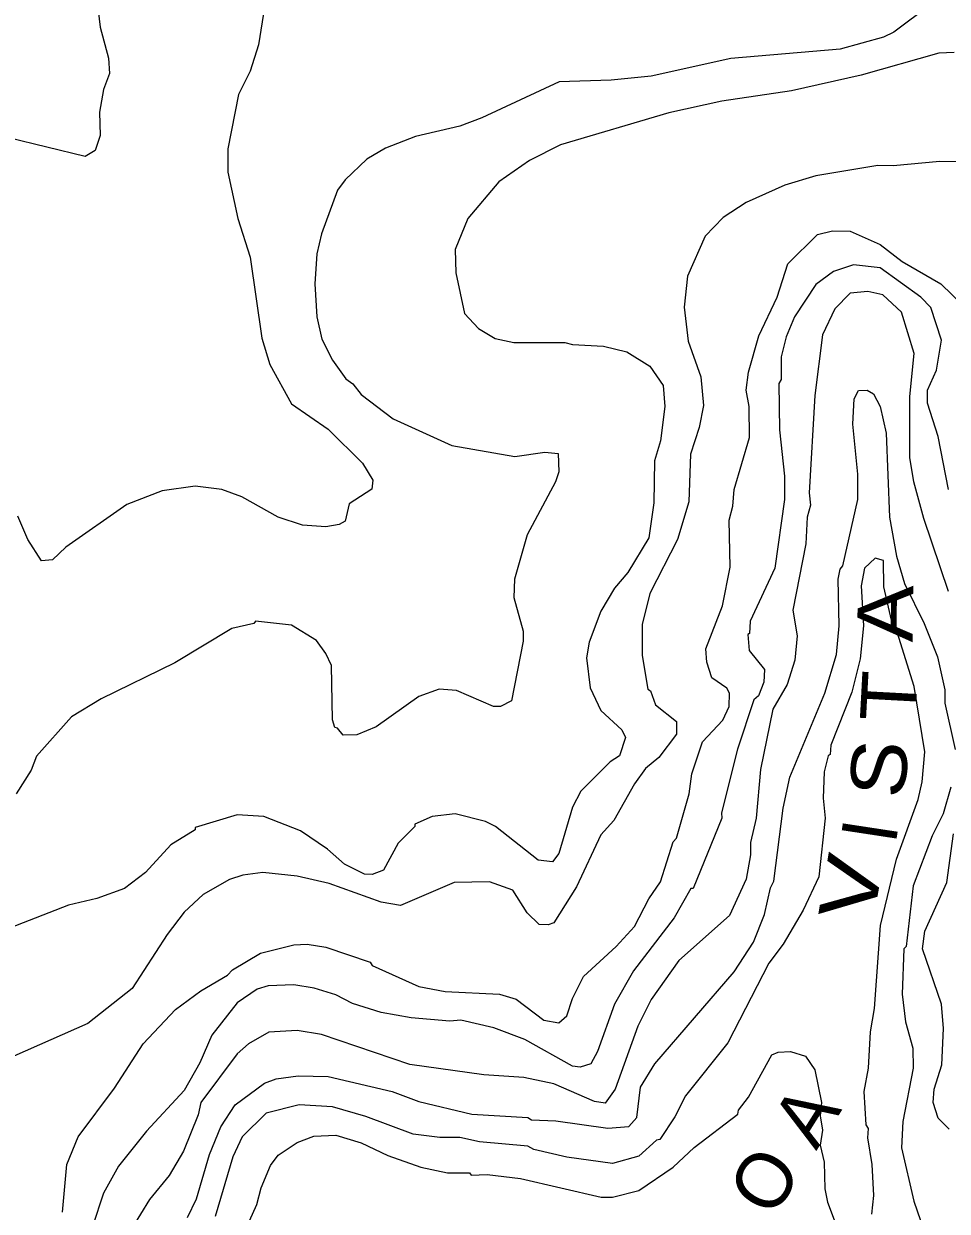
# Model space of a CAD drawing. Extents: x 265.7 to 292.1, y 7676.2 to 7704.2.
# Drawn here: x 274.191 to 275.523, y 7682.175 to 7683.888 of the extents above; entities that cross this region are included whole.
import ezdxf
from ezdxf.enums import TextEntityAlignment as Align

# ---------------------------------------------------------------- set-up
doc = ezdxf.new("R2010")
doc.units = 0
doc.header["$LTSCALE"] = 0.032
doc.layers.add('1', color=7, linetype='Continuous', lineweight=25)
doc.layers.add('2', color=7, linetype='Continuous', lineweight=13)
doc.layers.add('61', color=7, linetype='Continuous')

msp = doc.modelspace()

# ---------------------------------------------------------------- linework, layer by layer
at = {"layer": '1'}
for points in [[(275.4995, 7683.9157), (275.446, 7683.8758), (275.4309, 7683.8686), (275.3686, 7683.8511), (275.2106, 7683.8375), (275.0957, 7683.812), (275.0383, 7683.8064), (274.9633, 7683.804), (274.8515, 7683.7521), (274.8196, 7683.7402), (274.7558, 7683.725), (274.7127, 7683.7082), (274.6856, 7683.6923), (274.6544, 7683.6628), (274.6433, 7683.6476), (274.6201, 7683.5846), (274.6137, 7683.5558), (274.6105, 7683.5127), (274.6137, 7683.4649), (274.6209, 7683.433), (274.6361, 7683.4026), (274.6552, 7683.3755), (274.6656, 7683.3683), (274.6776, 7683.3531), (274.7239, 7683.318), (274.8085, 7683.2797), (274.8994, 7683.2638)], [(275.525, 7683.0691), (275.4891, 7683.1744), (275.4747, 7683.2271), (275.4692, 7683.2622), (275.4692, 7683.35), (275.4755, 7683.4122), (275.4572, 7683.472), (275.4301, 7683.4968), (275.4085, 7683.5016), (275.383, 7683.4992), (275.3606, 7683.4768), (275.3431, 7683.4393), (275.3319, 7683.3516), (275.3239, 7683.2111), (275.3255, 7683.1936), (275.3207, 7683.176), (275.3191, 7683.1377), (275.3, 7683.0419), (275.3064, 7683.0052), (275.3032, 7682.9701), (275.292, 7682.935), (275.2713, 7682.8991), (275.2537, 7682.8121), (275.2473, 7682.7419), (275.2393, 7682.7068), (275.2393, 7682.6893), (275.233, 7682.6541), (275.209, 7682.6015), (275.1356, 7682.5368), (275.0957, 7682.4802), (275.0766, 7682.4419), (275.0438, 7682.3509), (275.0295, 7682.331), (275.0143, 7682.3333), (274.9553, 7682.3589), (274.9122, 7682.3677), (274.8547, 7682.3716), (274.7478, 7682.3868), (274.6201, 7682.4299), (274.585, 7682.4355), (274.5443, 7682.4331), (274.5148, 7682.4163), (274.4988, 7682.402), (274.4462, 7682.3318), (274.4422, 7682.3142), (274.4214, 7682.2615), (274.4007, 7682.2264), (274.372, 7682.1921), (274.3464, 7682.1498)], [(274.8994, 7683.2638), (274.9425, 7683.2701), (274.9617, 7683.2678), (274.9625, 7683.2414), (274.9577, 7683.2271), (274.917, 7683.1505), (274.8986, 7683.0866)], [(274.8986, 7683.0866), (274.8978, 7683.0603), (274.9114, 7683.0116), (274.9114, 7682.9973), (274.8946, 7682.9111), (274.8787, 7682.9031), (274.8683, 7682.9031), (274.8148, 7682.9262), (274.7901, 7682.9278), (274.7606, 7682.9175), (274.6991, 7682.8736), (274.6712, 7682.8624), (274.6513, 7682.8616), (274.6433, 7682.872), (274.6393, 7682.8728), (274.6361, 7682.884), (274.6345, 7682.9621), (274.6265, 7682.9797), (274.613, 7682.9981), (274.577, 7683.0204), (274.5252, 7683.026), (274.5228, 7683.0228), (274.4909, 7683.0156), (274.4087, 7682.9661), (274.3025, 7682.9143), (274.2595, 7682.8879), (274.2092, 7682.8313), (274.2012, 7682.8113), (274.1796, 7682.777)], [(275.5258, 7682.2935), (275.5099, 7682.3094), (275.5027, 7682.3318), (275.5043, 7682.3509), (275.5154, 7682.386), (275.5178, 7682.4387), (275.5146, 7682.4738), (275.4875, 7682.5536), (275.4907, 7682.5791), (275.5226, 7682.6494), (275.5322, 7682.7196)]]:
    msp.add_lwpolyline(points, dxfattribs=at)
at = {"layer": '2'}
for points in [[(274.297, 7683.9149), (274.3009, 7683.883), (274.3129, 7683.8383), (274.3145, 7683.816), (274.3057, 7683.7928), (274.3001, 7683.7601), (274.3009, 7683.7266), (274.2938, 7683.7051), (274.2794, 7683.6963), (274.1685, 7683.7234), (274.1334, 7683.7402), (274.0807, 7683.7729), (274.0057, 7683.8375), (273.9259, 7683.8886)], [(274.5379, 7683.9117), (274.5292, 7683.8575), (274.5172, 7683.8192), (274.5004, 7683.7856), (274.4853, 7683.7074), (274.4853, 7683.6739), (274.4996, 7683.6069), (274.5172, 7683.551), (274.534, 7683.4345), (274.5459, 7683.3962), (274.577, 7683.3396), (274.6297, 7683.3029), (274.6792, 7683.2542), (274.6943, 7683.2295), (274.6927, 7683.2167), (274.66, 7683.1952), (274.6544, 7683.1704), (274.6457, 7683.1656), (274.6265, 7683.1624), (274.593, 7683.1648), (274.5579, 7683.176), (274.5052, 7683.2055), (274.4765, 7683.2159), (274.4382, 7683.2207), (274.3903, 7683.2143), (274.3393, 7683.1944), (274.2515, 7683.1329), (274.2323, 7683.1146), (274.2164, 7683.113), (274.1964, 7683.1441), (274.182, 7683.1776)], [(275.533, 7683.8463), (275.5107, 7683.8455), (275.3989, 7683.8136), (275.2984, 7683.7912), (275.1979, 7683.7761), (275.1213, 7683.7593), (274.9649, 7683.713), (274.9202, 7683.6907), (274.8763, 7683.6596), (274.8316, 7683.6069), (274.8132, 7683.5622), (274.814, 7683.5287), (274.8268, 7683.4697), (274.8468, 7683.4481), (274.8707, 7683.4337), (274.8978, 7683.4282), (274.9712, 7683.4282), (274.9824, 7683.425), (275.0271, 7683.4226), (275.0606, 7683.4146), (275.0941, 7683.3938), (275.1133, 7683.3659), (275.1157, 7683.3356), (275.1093, 7683.2861), (275.1005, 7683.2574), (275.0997, 7683.1968), (275.0925, 7683.1465), (275.0622, 7683.0962), (275.043, 7683.0739), (275.0231, 7683.0404), (275.0063, 7682.9957), (275.0024, 7682.9733), (275.0079, 7682.9302), (275.0231, 7682.8975), (275.0534, 7682.8696), (275.059, 7682.8584), (275.0502, 7682.8321), (275.0367, 7682.8233), (274.9944, 7682.781), (274.9824, 7682.7579), (274.9625, 7682.6908), (274.9537, 7682.6789), (274.9329, 7682.6813), (274.8715, 7682.7299), (274.8571, 7682.7371), (274.8132, 7682.7483), (274.7797, 7682.7443), (274.755, 7682.7331), (274.755, 7682.7299), (274.731, 7682.706), (274.7095, 7682.6669), (274.6935, 7682.6605), (274.6824, 7682.6613), (274.6536, 7682.6757), (274.6289, 7682.6972), (274.5898, 7682.7236), (274.5371, 7682.7443), (274.4988, 7682.7467), (274.4382, 7682.7283), (274.4382, 7682.7252), (274.4031, 7682.7036), (274.3664, 7682.6637), (274.3361, 7682.6406), (274.2962, 7682.6262), (274.2555, 7682.6166), (274.1701, 7682.5831)], [(275.6016, 7683.6875), (275.5123, 7683.6891), (275.4452, 7683.6827), (275.4229, 7683.6835), (275.3335, 7683.6683), (275.2888, 7683.6548), (275.233, 7683.63), (275.1995, 7683.6085), (275.1739, 7683.5814), (275.1484, 7683.5239), (275.1436, 7683.4792), (275.1492, 7683.4298), (275.1675, 7683.3787), (275.1715, 7683.3372), (275.1651, 7683.3053)], [(274.2467, 7682.1738), (274.2531, 7682.2424), (274.269, 7682.2823), (274.3217, 7682.3525), (274.3632, 7682.4163), (274.4095, 7682.4658), (274.4462, 7682.4929), (274.4845, 7682.5153), (274.4917, 7682.5233), (274.5324, 7682.5472), (274.5802, 7682.5592), (274.5994, 7682.56), (274.6265, 7682.556), (274.6904, 7682.5344), (274.6935, 7682.5296), (274.7606, 7682.4993), (274.7989, 7682.4921), (274.8771, 7682.4882), (274.901, 7682.481), (274.9409, 7682.4506), (274.9625, 7682.4467), (274.9744, 7682.457), (274.9824, 7682.4818), (274.9984, 7682.5137), (275.0454, 7682.5568), (275.0718, 7682.5855), (275.0925, 7682.6254), (275.1093, 7682.6501), (275.1276, 7682.7076), (275.1324, 7682.7132), (275.1508, 7682.777), (275.1543, 7682.8058), (275.1699, 7682.852), (275.1994, 7682.8832), (275.2082, 7682.9031), (275.209, 7682.9223), (275.205, 7682.9294), (275.1835, 7682.9446), (275.1763, 7682.9669), (275.1747, 7682.9861), (275.1987, 7683.0483), (275.2098, 7683.1042), (275.2082, 7683.172), (275.2138, 7683.192), (275.2154, 7683.2159), (275.2378, 7683.2909), (275.237, 7683.3356), (275.233, 7683.3595), (275.2362, 7683.3851), (275.2513, 7683.4377), (275.2777, 7683.4936), (275.2928, 7683.5415), (275.3359, 7683.5838), (275.3575, 7683.5893), (275.383, 7683.5885), (275.4261, 7683.5694), (275.458, 7683.5447), (275.5139, 7683.5127), (275.5458, 7683.4816)], [(275.3878, 7683.5399), (275.359, 7683.5303), (275.3335, 7683.5119), (275.3024, 7683.4649), (275.2904, 7683.4361), (275.2832, 7683.4074), (275.2832, 7683.3747)], [(275.525, 7683.2159), (275.5099, 7683.2925), (275.4947, 7683.3404), (275.4947, 7683.3595), (275.5075, 7683.3883), (275.5146, 7683.4313), (275.4995, 7683.4784), (275.4851, 7683.4936), (275.4261, 7683.5359), (275.3878, 7683.5399)], [(275.2832, 7683.3747), (275.28, 7683.3691), (275.2808, 7683.3021), (275.288, 7683.2351), (275.288, 7683.2015), (275.2745, 7683.1026), (275.2386, 7683.026), (275.2378, 7683.0084), (275.2354, 7683.0068), (275.237, 7682.9837), (275.2593, 7682.9566), (275.2585, 7682.9382), (275.2505, 7682.9183), (275.2441, 7682.9127), (275.2203, 7682.8417)], [(275.0638, 7682.2974), (275.075, 7682.3102), (275.0806, 7682.3541), (275.1013, 7682.3876), (275.2154, 7682.5201), (275.2433, 7682.5632), (275.2593, 7682.6031), (275.2681, 7682.6414), (275.2729, 7682.6509), (275.2864, 7682.7563), (275.296, 7682.801), (275.3463, 7682.9223), (275.363, 7682.9781), (275.367, 7683.0196), (275.3654, 7683.0866), (275.3686, 7683.101), (275.3726, 7683.1058), (275.3942, 7683.2015), (275.3942, 7683.2382), (275.387, 7683.3101), (275.3886, 7683.3468), (275.395, 7683.3587), (275.4077, 7683.3595), (275.4165, 7683.3539), (275.4261, 7683.3356), (275.4348, 7683.2973), (275.4396, 7683.176), (275.45, 7683.1201), (275.4612, 7683.0803), (275.4899, 7683.0228), (275.5091, 7682.9749), (275.5194, 7682.927), (275.5194, 7682.9079), (275.5346, 7682.8409)], [(275.1651, 7683.3053), (275.1524, 7683.267), (275.15, 7683.1983), (275.134, 7683.1441), (275.0941, 7683.0659), (275.083, 7683.0212), (275.083, 7682.9765)], [(275.4317, 7683.0755), (275.4309, 7683.1138), (275.4189, 7683.1169), (275.4037, 7683.1026), (275.3989, 7683.0771), (275.4021, 7683.0196), (275.3973, 7682.9717), (275.3854, 7682.9239), (275.3551, 7682.8472), (275.3543, 7682.8337), (275.3511, 7682.8321), (275.3455, 7682.8089), (275.3439, 7682.7706), (275.3471, 7682.7419), (275.3375, 7682.6573), (275.3152, 7682.6095), (275.2864, 7682.56), (275.2657, 7682.5328), (275.2066, 7682.4179), (275.1452, 7682.3413), (275.13, 7682.311), (275.1085, 7682.2783), (275.1037, 7682.2775), (275.0782, 7682.2544), (275.0399, 7682.244), (274.9744, 7682.2528), (274.9266, 7682.2639), (274.9178, 7682.2687), (274.8484, 7682.2751), (274.8196, 7682.2815), (274.7909, 7682.2815), (274.7526, 7682.2863), (274.684, 7682.3118), (274.6361, 7682.3254), (274.5882, 7682.3286), (274.5403, 7682.3166), (274.506, 7682.2823), (274.4925, 7682.2536), (274.4669, 7682.1674)], [(275.4811, 7682.769), (275.4867, 7682.7946), (275.4907, 7682.8377), (275.4755, 7682.9318), (275.4484, 7683.018), (275.4428, 7683.0276), (275.4317, 7683.0755)], [(275.083, 7682.9765), (275.0909, 7682.9278), (275.0949, 7682.9254), (275.1021, 7682.9055), (275.1324, 7682.8816), (275.1324, 7682.8632), (275.1069, 7682.8297), (275.0877, 7682.8137), (275.0718, 7682.7914), (275.0422, 7682.7387), (275.0231, 7682.718), (274.988, 7682.643), (274.9553, 7682.5911), (274.9473, 7682.5879), (274.9345, 7682.5887), (274.917, 7682.6055), (274.8962, 7682.6382), (274.8627, 7682.6501), (274.8116, 7682.6493), (274.7342, 7682.6158), (274.7063, 7682.6206), (274.6313, 7682.6478), (274.585, 7682.6581), (274.5356, 7682.6637), (274.5068, 7682.6597), (274.4877, 7682.6533), (274.4494, 7682.6318), (274.4222, 7682.6063), (274.3975, 7682.5743), (274.3472, 7682.4961), (274.2834, 7682.4459), (274.1765, 7682.3988)], [(275.2203, 7682.8417), (275.1971, 7682.7499), (275.1979, 7682.7419), (275.1564, 7682.6406), (275.1532, 7682.6406), (275.1292, 7682.5983), (275.0702, 7682.5217), (275.043, 7682.4738), (275.0183, 7682.4052), (275.0087, 7682.3876), (274.9936, 7682.3828), (274.9824, 7682.3844), (274.9138, 7682.4227), (274.8691, 7682.4395), (274.8212, 7682.4507), (274.8053, 7682.4491), (274.7494, 7682.4538), (274.7063, 7682.4618), (274.6648, 7682.4746), (274.6409, 7682.4874), (274.6098, 7682.4969), (274.5802, 7682.5017), (274.5435, 7682.5001), (274.5276, 7682.4953), (274.4988, 7682.4754), (274.4621, 7682.4291), (274.4446, 7682.3892), (274.4222, 7682.3493), (274.368, 7682.2903), (274.3273, 7682.24), (274.3057, 7682.2009), (274.2898, 7682.153)], [(275.5282, 7682.7866), (275.517, 7682.7483), (275.5011, 7682.7164), (275.4739, 7682.6446), (275.4636, 7682.5568), (275.4604, 7682.5536), (275.458, 7682.4882), (275.4628, 7682.4483), (275.4732, 7682.41), (275.474, 7682.3812), (275.4588, 7682.3046), (275.4572, 7682.2663), (275.4747, 7682.1897), (275.4947, 7682.1323), (275.5043, 7682.1131), (275.545, 7681.9791)], [(275.4141, 7682.1706), (275.4173, 7682.1977), (275.4149, 7682.2424), (275.4085, 7682.2807), (275.4093, 7682.2942), (275.4061, 7682.2998), (275.4029, 7682.3477), (275.4093, 7682.3812), (275.4125, 7682.4339), (275.4181, 7682.4674), (275.4269, 7682.5871), (275.45, 7682.6829), (275.4811, 7682.769)], [(274.5076, 7682.1418), (274.5268, 7682.1849), (274.5332, 7682.2089), (274.5467, 7682.2408), (274.5579, 7682.256), (274.585, 7682.2743), (274.609, 7682.2831), (274.6409, 7682.2847), (274.6776, 7682.2735), (274.7159, 7682.2552), (274.7638, 7682.2384), (274.8021, 7682.2304), (274.834, 7682.2304), (274.8364, 7682.2272), (274.8595, 7682.228), (274.9074, 7682.2224), (275.0239, 7682.1953), (275.0399, 7682.1953), (275.0782, 7682.2049), (275.1276, 7682.2384), (275.158, 7682.2671), (275.221, 7682.315), (275.2218, 7682.3206), (275.2362, 7682.3397), (275.2697, 7682.4004), (275.2793, 7682.4044), (275.2968, 7682.4052), (275.3184, 7682.3988), (275.3319, 7682.3788), (275.3415, 7682.3318), (275.3399, 7682.3126), (275.3431, 7682.2919), (275.3399, 7682.2703), (275.3455, 7682.2456), (275.3463, 7682.2073), (275.3503, 7682.1881), (275.379, 7682.1115)], [(274.427, 7682.1658), (274.4398, 7682.1929), (274.4589, 7682.2568), (274.4749, 7682.2967), (274.4956, 7682.3286), (274.5379, 7682.3597), (274.5547, 7682.3661), (274.5866, 7682.3701), (274.6297, 7682.3693), (274.7223, 7682.3477), (274.7606, 7682.3334)], [(274.7606, 7682.3334), (274.8372, 7682.315), (274.9178, 7682.3102), (274.9234, 7682.307), (274.9585, 7682.3054), (275.0335, 7682.295), (275.0638, 7682.2974)]]:
    msp.add_lwpolyline(points, dxfattribs=at)

# ---------------------------------------------------------------- texts
at = {"layer": '61'}
for s, rotation, width, p in [('A', 89.228, 1.15, (275.4735, 7683.0365)), ('T', 86.928, 1.1, (275.4787, 7682.9157)), ('S', 84.283, 1.15, (275.4643, 7682.8094)), ('V', 80.372, 1.3, (275.4235, 7682.6353))]:
    msp.add_text(s, height=0.08, rotation=rotation, dxfattribs=dict(at, width=width)).set_placement(p, align=Align.CENTER)
for s, rotation, p in [('I', 81.347, (275.4507, 7682.7175)), ('A', 57.952, (275.3529, 7682.2918)), ('O', 57.633, (275.293, 7682.1982))]:
    msp.add_text(s, height=0.08, rotation=rotation, dxfattribs=at).set_placement(p, align=Align.CENTER)

doc.saveas('drawing.dxf')
